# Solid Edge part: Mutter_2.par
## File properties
Sűrűség: 0,000 kg/m^3
Pontosság: 0,990
Author: ahadarics
Last saved by: ahadarics
Revision: 77
Username: ahadarics
Dokumentum tartalom típus: 0
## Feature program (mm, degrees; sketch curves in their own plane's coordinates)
base feature "unnamed BaseFeature 1"
thread "unnamed Thread 1"
chamfer "unnamed Chamfer 1"
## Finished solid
Body 1: solid body, 25 faces, 64 edges, 40 vertices.
  Faces by surface: plane 14, cone 6, cylinder 5
  Edges by curve: line 40, circle 24
Bounding box of the edges (mm): 44.721 x 44.721 x 7.000, from (-22.3607, -22.3607, 0) to (22.3607, 22.3607, 7).
Cylindrical faces by radius (mm): R14.188 x1, R22.5 x4
Conical faces (half-angle, radius in mm at the cone's reference point): 45 deg R14.188 x1, 45 deg R15.188 x1, 45 deg R21.75 x4
Planar faces by outward normal: +x 3, +y 3, +z 1, -x 3, -y 3, -z 1
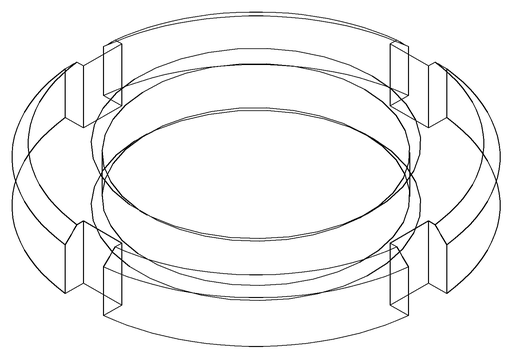
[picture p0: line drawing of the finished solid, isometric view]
